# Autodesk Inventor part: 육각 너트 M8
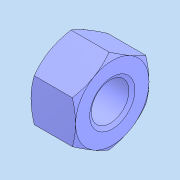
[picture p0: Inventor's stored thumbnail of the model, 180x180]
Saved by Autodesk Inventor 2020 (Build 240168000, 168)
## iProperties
Created: 2024-11
Part Number: 육각 너트 M8
Material: 강철, 연강
Description: 6각 너트 및 6각 가는 너트
Document SubType Name: Modeling
Designer: 1강의실14
Density: 7.85 g/cm^3
Appearance: 기본값
Author: jhkim
Sending System: Autodesk Inventor 2025
Preprocessor: ST-DEVELOPER v20
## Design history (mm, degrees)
node "육각 너트 M81"
node "솔리드1"
body "Solid1"
